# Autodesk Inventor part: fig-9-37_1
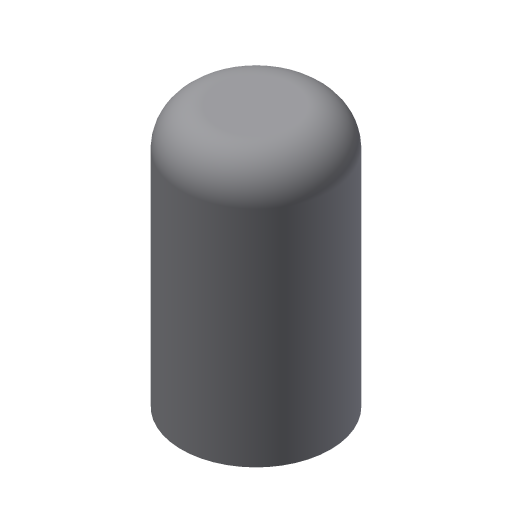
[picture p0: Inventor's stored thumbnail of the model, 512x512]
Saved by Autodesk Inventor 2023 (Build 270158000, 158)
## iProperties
Created: 2013-03
Part Number: fig-9-37_1
Material: Generic
Document SubType Name: Modeling
Designer: CADCIM
Density: 1 g/cm^3
Appearance: Default
Author: CADCIM
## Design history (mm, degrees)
sketch "Sketch1"
  geometry: C1 r 10 at (0, 0); 1 further point
  constraints: 1 centre point, 1 coincident
  dimensions: "d0" = 20 diameter of C1
extrude "Extrusion1" new body sketch "Sketch1" distance "d2" = 35; taper "d3" = 0 deg
fillet "Fillet1" dims "d4" = 5
shell "Shell1" dims "d5" = 2
body "Solid1"
